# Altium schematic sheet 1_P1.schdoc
size 365 x 365 mm; Symbol: Drawing-Symbol_A4; Device: Drawing-Symbol_A4; @Project Name: MSDRV4; @Page Count: 1; @Update Date: 2025-04-11; @Create Date: 2025-01-27; @Schematic Name: Schematic1; @Page No: 1; @Page Name: P1; Company: EasyEDA.com; Version: V1.0; Page Size: A4; @Create Time: 14:19:29; @Update Time: 18:21:54; Width: 1400; Height: 1400; Region Start: 1; X Region Count: 6; Y Region Count: 4; Blade Width: 10; Title Block Position: 3; @Board Name: Board1
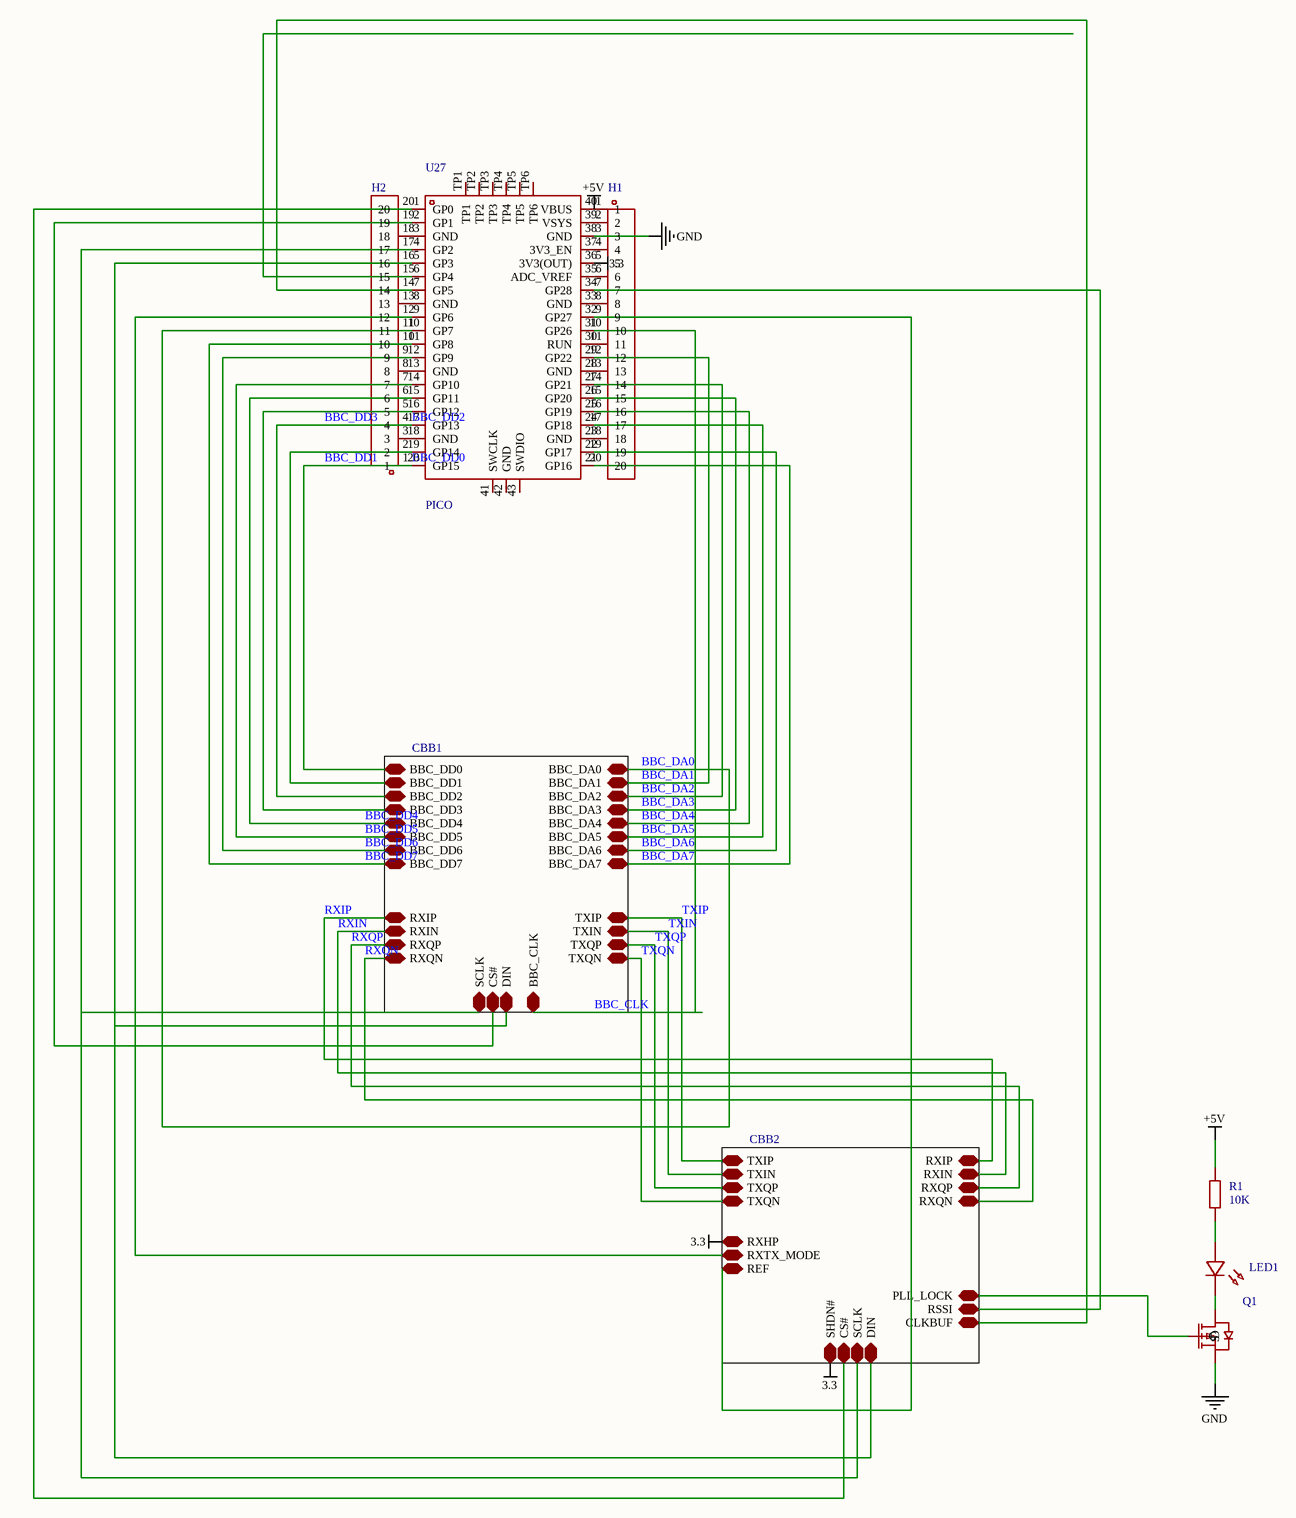
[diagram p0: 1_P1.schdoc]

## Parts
H1  (no value)  [HDR-TH_20P-P2.54-V-M-1]
H2  (no value)  [HDR-TH_20P-P2.54-V-M-1]
LED1  (no value)  [LED0603-R-RD]
Q1  (no value)  [SOT-23_L2.9-W1.3-P1.90-LS2.4-BR]
R1  10K  [R0603]
U27  PICO  [comm-smd_l51.0-w21.0-p2.54_sc0916]

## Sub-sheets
CBB1 = ?: BBC_DD0, BBC_DD1, BBC_DD2, BBC_DD3, BBC_DD4, BBC_DD5, BBC_DD6, BBC_DD7, SCLK, CS#, DIN, RXIP, RXIN, RXQP, RXQN, BBC_CLK, BBC_DA0, BBC_DA1, BBC_DA2, BBC_DA3, BBC_DA4, BBC_DA5, BBC_DA6, BBC_DA7, TXIP, TXIN, TXQP, TXQN  | Symbol: BBC_2024_REUSE; Device: BBC_2024_REUSE; Relevance: []
CBB2 = ?: SHDN#, CS#, SCLK, DIN, RSSI, RXTX_MODE, RXHP, TXIP, TXIN, TXQP, TXQN, PLL_LOCK, CLKBUF, RXIP, RXIN, RXQP, RXQN, REF  | Symbol: MAX2831_2024_REUSE; Device: MAX2831_2024_REUSE; Relevance: []

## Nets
3.3: H1.5 U27.36(3V3(OUT)) ; sheet CBB2/SHDN#, sheet CBB2/RXHP
+5V: H1.1 R1.2 U27.40(VBUS)
GND: H1.3 Q1.2(S) U27.38(GND)
BBC_CLK: H1.10 U27.31(GP26) ; sheet CBB1/BBC_CLK
BBC_DA0: H2.11 U27.10(GP7) ; sheet CBB1/BBC_DA0
BBC_DA1: H1.12 U27.29(GP22) ; sheet CBB1/BBC_DA1
BBC_DA2: H1.14 U27.27(GP21) ; sheet CBB1/BBC_DA2
BBC_DA3: H1.15 U27.26(GP20) ; sheet CBB1/BBC_DA3
BBC_DA4: H1.16 U27.25(GP19) ; sheet CBB1/BBC_DA4
BBC_DA5: H1.17 U27.24(GP18) ; sheet CBB1/BBC_DA5
BBC_DA6: H1.19 U27.22(GP17) ; sheet CBB1/BBC_DA6
BBC_DA7: H1.20 U27.21(GP16) ; sheet CBB1/BBC_DA7
BBC_DD0: H2.1 U27.20(GP15) ; sheet CBB1/BBC_DD0  [also labelled BBC_DD1]
BBC_DD2: H2.4 U27.17(GP13) ; sheet CBB1/BBC_DD2  [also labelled BBC_DD3]
BBC_DD4: H2.6 U27.15(GP11) ; sheet CBB1/BBC_DD4
BBC_DD5: H2.7 U27.14(GP10) ; sheet CBB1/BBC_DD5
BBC_DD6: H2.9 U27.12(GP9) ; sheet CBB1/BBC_DD6
BBC_DD7: H2.10 U27.11(GP8) ; sheet CBB1/BBC_DD7
RXIN: sheet CBB1/RXIN, sheet CBB2/RXIN
RXIP: sheet CBB1/RXIP, sheet CBB2/RXIP
RXQN: sheet CBB1/RXQN, sheet CBB2/RXQN
RXQP: sheet CBB1/RXQP, sheet CBB2/RXQP
TXIN: sheet CBB1/TXIN, sheet CBB2/TXIN
TXIP: sheet CBB1/TXIP, sheet CBB2/TXIP
TXQN: sheet CBB1/TXQN, sheet CBB2/TXQN
TXQP: sheet CBB1/TXQP, sheet CBB2/TXQP
NetH1_2: H1.2 U27.39(VSYS)
NetH1_4: H1.4 U27.37(3V3_EN)
NetH1_6: H1.6 U27.35(ADC_VREF)
NetH1_7: H1.7 U27.34(GP28) ; sheet CBB2/RSSI
NetH1_8: H1.8 U27.33(GND)
NetH1_9: H1.9 U27.32(GP27) ; sheet CBB2/REF
NetH1_11: H1.11 U27.30(RUN)
NetH1_13: H1.13 U27.28(GND)
NetH1_18: H1.18 U27.23(GND)
NetH2_2: H2.2 U27.19(GP14) ; sheet CBB1/BBC_DD1
NetH2_3: H2.3 U27.18(GND)
NetH2_5: H2.5 U27.16(GP12) ; sheet CBB1/BBC_DD3
NetH2_8: H2.8 U27.13(GND)
NetH2_12: H2.12 U27.9(GP6) ; sheet CBB2/RXTX_MODE
NetH2_13: H2.13 U27.8(GND)
NetH2_14: H2.14 U27.7(GP5) ; sheet CBB2/CLKBUF
NetH2_15: H2.15 U27.6(GP4)
NetH2_16: H2.16 U27.5(GP3) ; sheet CBB1/DIN, sheet CBB2/DIN
NetH2_17: H2.17 U27.4(GP2) ; sheet CBB1/SCLK, sheet CBB2/SCLK
NetH2_18: H2.18 U27.3(GND)
NetH2_19: H2.19 U27.2(GP1) ; sheet CBB1/CS#
NetH2_20: H2.20 U27.1(GP0) ; sheet CBB2/CS#
NetLED1_1: LED1.1(A) R1.1
NetLED1_2: LED1.2(C) Q1.3(D)
NetQ1_1: Q1.1(G) ; sheet CBB2/PLL_LOCK

Not connected (* = marked no-connect by the designer): U27 41(SWCLK) 42(GND) 43(SWDIO) TP1 TP2 TP3 TP4 TP5 TP6

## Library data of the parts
H1 H2 = HDR-M_2.54_1x20P: Symbol: HDR_2.54-1x20P; Convert to PCB: yes
LED1 = LED_0603-R: Symbol: LED_R; Convert to PCB: yes
Q1 = P_MOS: Convert to PCB: yes
R1 = Res_0603: Symbol: Res; Convert to PCB: yes
U27 = PICO: Manufacturer: Raspberry Pi(树莓派); Add into BOM: yes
